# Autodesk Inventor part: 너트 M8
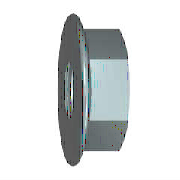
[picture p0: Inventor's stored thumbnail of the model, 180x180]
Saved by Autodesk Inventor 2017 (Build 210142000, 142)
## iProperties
Created: 2015-09
Part Number: 너트 M8
Material: 스테인리스강
Description: 플랜지붙이 6각 너트 - 일반 스레드
Document SubType Name: Modeling
Standard: ISO 4161
Designer: mduedu
Standard Revision: 2판 1999-03-15
Standards Organization: ISO
Language: ko-KR
Size Designation: M8
Categories: <MemberInstance><Categories><Category DisplayName="조임쇠" InternalName="e4da775c-781d-43d5-af7c-5136215cf5a6" Mnemonic="FSTN"><Category DisplayName="너트" InternalN
Density: 8.08 g/cm^3
Appearance: 기본값
Author: mduedu
IsCustomPart: 1
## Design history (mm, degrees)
sketch "스케치1"
  geometry: L1 (-1.844, 0)-(9.641, 0) reference; L2 (3.107, 6.5)-(2.288, 8.257); L3 (3.107, 6.5)-(8, 6.5); L4 (8, 6.5)-(8, 0); L5 (3.107, 6.5)-(3.107, 0); L6 (0, -1.835)-(0, 11.01) reference; A1 r 1.2 centre (1.2, 7.75) between (2.288, 8.257) and (0, 7.75); 1 further point
  constraints: 8 end point, 3 point on line, 2 perpendicular, 2 point on circle, 2 tangent, 1 centre point, 1 parallel
  dimensions: "d2" = 13 diameter of L3 L1 (= SW); "d4" = 17.9 dimension on A1 L1 (= LADI); "d5" = 1.2 radius of A1 (= PHH); "d15" = 8 distance between parallel lines of L4 L6 (= KOH); "d16" = 25 deg angle of L6 L2 (= KEWI)
revolve "링" sketch "스케치1" stored, may be unused: angle "d8" = 90 deg
sketch "스케치2"
  geometry: L1 (-6.5, -3.753)-(-6.5, 3.753); L2 (-6.5, 3.753)-(0, 7.506); L3 (0, 7.506)-(6.5, 3.753); L4 (6.5, 3.753)-(6.5, -3.753); L5 (6.5, -3.753)-(0, -7.506); L6 (0, -7.506)-(-6.5, -3.753); C1 r 4.9 at (0, 0); C2 r 7.75 at (0, 0) reference; 1 further point
  constraints: 12 end point, 1 centre point, 1 coincident, 1 vertical, 11 other
  dimensions: "d6" = 15.01111 distance of L5.end L2.end (= 1.1547 x SW)
extrude "본체" join sketch "스케치2" distance "d7" = 8 (= KOH); taper "d9" = 0 deg
sketch "스케치3"
  geometry: L1 (2.638, 7.506)-(8, 7.506) reference; L2 (8, 3.753)-(8, 7.506) reference; L3 (0, -7.75)-(0, 7.75) reference; L4 (-1.6, 0)-(9.6, 0) reference; L5 (7.419, 7.506)-(8, 6.5)
  constraints: 2 end point, 2 point on line
  dimensions: "d10" = 30 deg angle of L2 L5 (= ANG1); "d11" = 13 diameter of L5.end L4 (= SW0)
revolve "모따기1" sketch "스케치3" stored, may be unused: angle "d24" = 90 deg
sketch "스케치4"
  geometry: C1 r 7.75 at (0, 0) reference; 1 further point
  constraints: 1 coincident
hole "스레드" sketch "스케치4" at (0, 0) diameter "d25" = 6.647; stored, may be unused: countersink angle "d29" = 82 deg, drill point angle "d31" = 118 deg; dims "d26" = 6, "d27" = 4, "d28" = 2, "d30" = 8
workaxis "Work Axis1"
workplane "Work Plane1"
body "Solid1"
chamfer "모따기2" distance "d12" = 0.67658 (= -0.5 x GD1 + 0.5 x NND); stored, may be unused: angle "d13" = 30 deg, second distance "d46" = 0.67658 (= -0.5 x GD1 + 0.5 x NND)
chamfer "모따기3" distance "d51" = 0.67658 (= -0.5 x GD1 + 0.5 x NND); stored, may be unused: second distance "d52" = 2, angle "d53" = 45 deg
other parameters: "ANG1" = 30 deg [user parameter; used in 1 equation term], "KEWI" = 25 deg [user parameter; used in 1 equation term], "NND" = 8 [user parameter; used in 4 equation terms], "LADI" = 17.9 [user parameter; used in 2 equation terms], "SW" = 13 [user parameter; used in 3 equation terms], "PHH" = 1.2 [user parameter; used in 3 equation terms], "KOH" = 8 (= NND) [user parameter; used in 2 equation terms], "SW0" = 13 [user parameter; used in 1 equation term], "GD1" = 6.64684 (computed from THREADDIA, PTC, TOA) [user parameter; used in 3 equation terms], "d1" = 17.9 (= LADI), "d3" = 1.2 (= PHH), "d45" = 0, "d47" = 0, "d49" = 0, "d54" = 0, "GUL" = 0.67658 (= 0.541266 x PTC) [user parameter], "TPU" = 8 (computed from PTC) [user parameter], "RR" = 1.2 (= PHH) [user parameter], "THREADDIA" = 8 [user parameter; used in 1 equation term], "TOA" = 30 deg [user parameter; used in 1 equation term], "PTC" = 1.25 [user parameter; used in 4 equation terms], "GAL" = 0.67658 (= 0.541266 x PTC) [user parameter], "E0" = 15.015 (= 1.155 x SW) [user parameter]
